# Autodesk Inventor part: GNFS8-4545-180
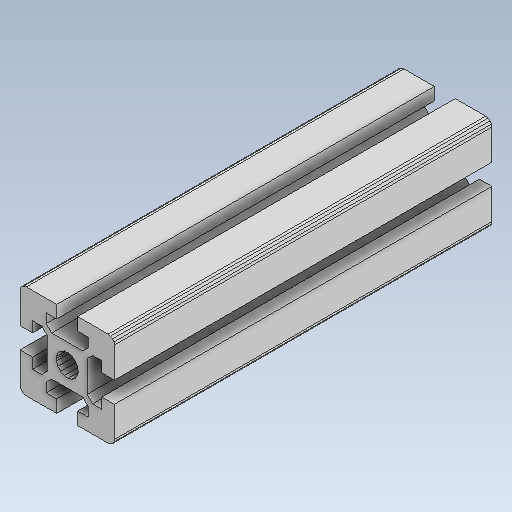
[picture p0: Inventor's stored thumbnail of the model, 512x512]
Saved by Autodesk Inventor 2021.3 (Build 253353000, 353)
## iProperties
Created: 2022-02
Part Number: GNFS8-4545-180
Material: 一般
Document SubType Name: Modeling
Designer: kengo
Density: 1 g/cm^3
Appearance: 既定
Author: kengo
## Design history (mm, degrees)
feature "GNFS8-4545-180"
node "ソリッド1"
